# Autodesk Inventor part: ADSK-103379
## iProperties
Shininess: 0.0
Created: 2001-01
Part Number: ADSK-103379
Document SubType Name: Modeling
Stock Number: ADSK-103379
Density: 1 g/cm^3
Density: 0.0
Volumn: 0.0
Area: 0.0
PropertySet Name: Model Information
Control State: 0
Master: False
Checked Out: False
Author: gao
